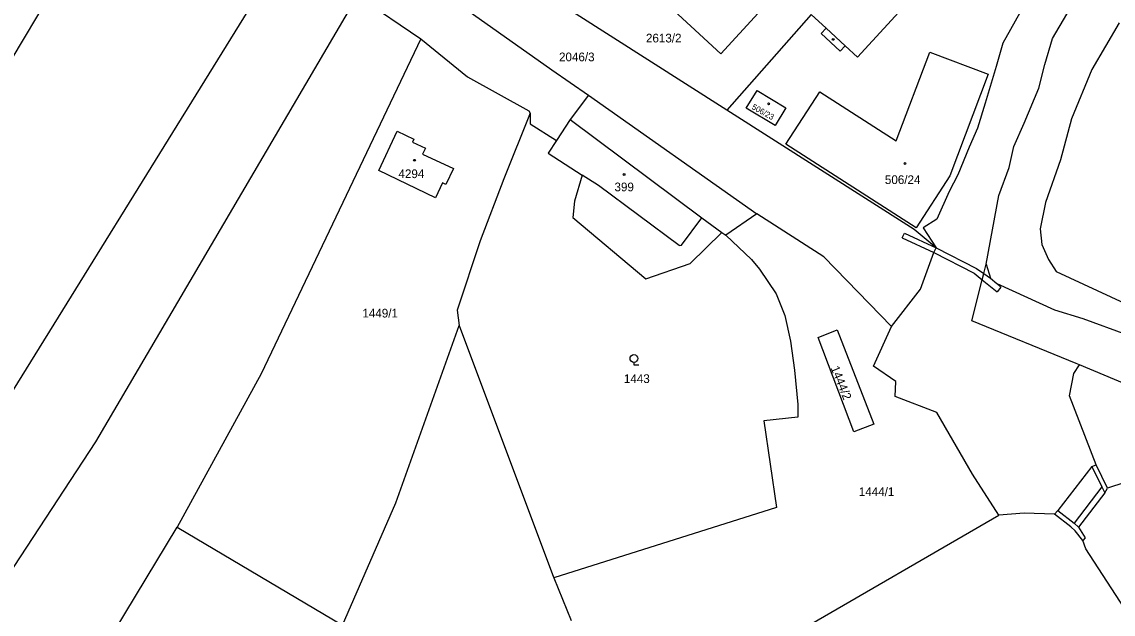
# Model space of a CAD drawing. Extents: x -679220 to -673243, y -1075091 to -1066557.
# Drawn here: x -677237.5 to -677024.2, y -1070909.6 to -1070793.9 of the extents above; entities that cross this region are included whole.
import ezdxf

# ---------------------------------------------------------------- set-up
doc = ezdxf.new("R2010")
doc.units = 0
for name, color, linetype in [('Hranice parcel', 7, 'Continuous'), ('Parcelní čísla', 7, 'Continuous'), ('Vnitřní kresba', 7, 'Continuous'), ('Značky budov', 7, 'Continuous'), ('Značky kultur', 7, 'Continuous')]:
    doc.layers.add(name, color=color, linetype=linetype)

msp = doc.modelspace()

# ---------------------------------------------------------------- linework, layer by layer
at = {"layer": 'Hranice parcel'}
for p, q in [((-677171.84, -1070788.87), (-677159.45, -1070797.23)), ((-677099.68, -1070811.19), (-677129.85, -1070791.98)), ((-677083.16, -1070792.51), (-677099.68, -1070811.19)), ((-677130.31, -1070813.04), (-677132.99, -1070817.11)), ((-677100.63, -1070835.07), (-677099.86, -1070835.63)), ((-677207.11, -1070892.64), (-677174.77, -1070911.8)), ((-677133.49, -1070902.55), (-677130.07, -1070910.86))]:
    msp.add_line(p, q, dxfattribs=at)
for points in [[(-677203.57, -1070759.78), (-677198.39, -1070762.15), (-677163.69, -1070784.55), (-677154.72, -1070788.54), (-677133.88, -1070803.28), (-677126.71, -1070808.28), (-677130.31, -1070813.04)], [(-677079.67, -1070777.1), (-677100.85, -1070800.17), (-677119.25, -1070783.14), (-677097.77, -1070760.15)], [(-677364.04, -1070987.23), (-677362.94, -1070980.54), (-677338.56, -1070950.82), (-677313.04, -1070919.03), (-677289.25, -1070883.76), (-677247.04, -1070813.86), (-677224.46, -1070776.16)], [(-677048.97, -1070841.27), (-677046.53, -1070827.88), (-677044.52, -1070822.41), (-677043.55, -1070818.31), (-677041.55, -1070813.73), (-677038.68, -1070806.91), (-677037.55, -1070802.28), (-677036.01, -1070797.18), (-677033.25, -1070792.43), (-677028.32, -1070784.52), (-677023.72, -1070776.62)], [(-677353.59, -1071009.21), (-677311.42, -1070962.52), (-677281.85, -1070927.39), (-677267.88, -1070909.25), (-677253.05, -1070888.24), (-677185.28, -1070778.87)], [(-677059.31, -1070777.52), (-677055.75, -1070780.81), (-677074.12, -1070800.85), (-677076.57, -1070798.6), (-677077.52, -1070799.64), (-677081.23, -1070796.22), (-677080.27, -1070795.18), (-677083.16, -1070792.51)], [(-677039.39, -1070786.77), (-677045.73, -1070798.1), (-677047.04, -1070802.64), (-677049.19, -1070809.83), (-677050.66, -1070814.68), (-677052.34, -1070818.42), (-677054.53, -1070823.8), (-677056.21, -1070827.09), (-677058.65, -1070832.51), (-677061.33, -1070834.18), (-677058.79, -1070838.11)], [(-677340.87, -1071024.47), (-677300.46, -1070979.79), (-677271.33, -1070945.13), (-677251.29, -1070919.02), (-677223.02, -1070875.98), (-677171.84, -1070788.87)], [(-677022.97, -1070794.1), (-677028.35, -1070803.23), (-677032.28, -1070812.9), (-677034.49, -1070820.9), (-677037.37, -1070829.22), (-677038.43, -1070834.4), (-677038.09, -1070837.4), (-677036.83, -1070840.36), (-677035.28, -1070842.73), (-677005.93, -1070856.29)], [(-677159.45, -1070797.23), (-677190.71, -1070862.68), (-677207.11, -1070892.64)], [(-677159.45, -1070797.23), (-677150.34, -1070804.67), (-677138.35, -1070811.34), (-677138.11, -1070811.79)], [(-677081.48, -1070807.61), (-677066.56, -1070817.17), (-677060.01, -1070799.83), (-677048.59, -1070804.17), (-677056.09, -1070823.99), (-677062.66, -1070834.18), (-677088.12, -1070817.82), (-677081.48, -1070807.61)], [(-677090.2, -1070814.2), (-677095.89, -1070810.83), (-677093.73, -1070807.34), (-677088.12, -1070810.73), (-677090.2, -1070814.2)], [(-677058.79, -1070838.11), (-677063.08, -1070834.48), (-677099.68, -1070811.19)], [(-677138.11, -1070811.79), (-677143.27, -1070824.61), (-677147.87, -1070836.71), (-677152.38, -1070850.24), (-677151.99, -1070853.28)], [(-677138.11, -1070811.79), (-677138.11, -1070813.87), (-677132.99, -1070817.11)], [(-677130.31, -1070813.04), (-677104.56, -1070832.23), (-677100.63, -1070835.07)], [(-677153.11, -1070822.6), (-677154.59, -1070825.7), (-677155.21, -1070825.41), (-677156.59, -1070828.29), (-677167.71, -1070822.98), (-677164.09, -1070815.28), (-677160.85, -1070816.84), (-677161.11, -1070817.41), (-677158.55, -1070818.62), (-677159.13, -1070819.8), (-677153.11, -1070822.6)], [(-677132.99, -1070817.11), (-677134.61, -1070819.57), (-677127.92, -1070823.86), (-677129.43, -1070828.99), (-677129.8, -1070832.15), (-677115.47, -1070844.14), (-677106.81, -1070841.14), (-677100.63, -1070835.07)], [(-677067.5, -1070853.44), (-677076.25, -1070844.46), (-677080.74, -1070839.83), (-677093.84, -1070831.44), (-677099.86, -1070835.63)], [(-677099.86, -1070835.63), (-677094.86, -1070840.34), (-677093.26, -1070842.27), (-677090.04, -1070847.06), (-677088.32, -1070851.27), (-677087.23, -1070856.33), (-677086.43, -1070862), (-677085.79, -1070868.68), (-677085.78, -1070871.18), (-677092.45, -1070871.86), (-677089.95, -1070888.83), (-677133.49, -1070902.55)], [(-677067.5, -1070853.44), (-677061.85, -1070846.17), (-677059.22, -1070839), (-677058.79, -1070838.11)], [(-677030.74, -1070860.94), (-677031.4, -1070860.66), (-677051.79, -1070852.33), (-677049.75, -1070844.31), (-677049.44, -1070843.12), (-677048.97, -1070841.27)], [(-677048.97, -1070841.27), (-677048.15, -1070843.99), (-677046.93, -1070845.02), (-677035.63, -1070850.17), (-677030.09, -1070851.88), (-677021.57, -1070855), (-677011.01, -1070859.1), (-677002.76, -1070862.36), (-676990.12, -1070867.28), (-676983.42, -1070869.86)], [(-677174.77, -1070911.8), (-677164.38, -1070887.87), (-677151.99, -1070853.28)], [(-677151.99, -1070853.28), (-677133.71, -1070901.92), (-677133.49, -1070902.55)], [(-677046.51, -1070890.3), (-677051.64, -1070882.27), (-677058.64, -1070870.25), (-677066.74, -1070867.15), (-677066.67, -1070864.21), (-677071.02, -1070861.17), (-677067.5, -1070853.44)], [(-677081.79, -1070855.6), (-677078.09, -1070854.08), (-677070.97, -1070872.55), (-677074.82, -1070874.01), (-677081.79, -1070855.6)], [(-676999.51, -1070876.63), (-677025.25, -1070885.02), (-677027.52, -1070880.46), (-677032.67, -1070866.98), (-677031.85, -1070862.65), (-677030.74, -1070860.94)], [(-676999.51, -1070876.63), (-677001.05, -1070873.4), (-677030.74, -1070860.94)], [(-677022.03, -1070908.42), (-677029.52, -1070896.85), (-677030.1, -1070895.25), (-677031.58, -1070893.38), (-677032.45, -1070892.61), (-677035.63, -1070890.11), (-677041.58, -1070889.89), (-677046.51, -1070890.3)], [(-677119.16, -1070937.01), (-677086.34, -1070913.35), (-677046.51, -1070890.3)], [(-677320.1, -1071047.08), (-677278.77, -1070997), (-677249.46, -1070958.04), (-677231.5, -1070933.09), (-677207.11, -1070892.64)]]:
    msp.add_lwpolyline(points, dxfattribs=at)
at = {"layer": 'Vnitřní kresba'}
for p, q in [((-677080.27, -1070795.18), (-677076.57, -1070798.6)), ((-677126.71, -1070808.28), (-677093.84, -1070831.44)), ((-677124.74, -1070825.9), (-677127.92, -1070823.86)), ((-677108.99, -1070837.61), (-677124.74, -1070825.9)), ((-677108.53, -1070837.54), (-677104.56, -1070832.23)), ((-677065.39, -1070836.14), (-677064.97, -1070835.23)), ((-677065.39, -1070836.14), (-677059.22, -1070839)), ((-677064.97, -1070835.23), (-677058.79, -1070838.11)), ((-677108.99, -1070837.61), (-677108.53, -1070837.54)), ((-677058.79, -1070838.11), (-677050.87, -1070842.15)), ((-677059.22, -1070839), (-677051.31, -1070843.04)), ((-677051.31, -1070843.04), (-677049.75, -1070844.31)), ((-677050.87, -1070842.15), (-677049.44, -1070843.12)), ((-677049.44, -1070843.12), (-677048.15, -1070843.99)), ((-677049.75, -1070844.31), (-677046.84, -1070846.67)), ((-677046.93, -1070845.02), (-677046.09, -1070845.79)), ((-677046.09, -1070845.79), (-677046.84, -1070846.67)), ((-677028.36, -1070880.78), (-677034.97, -1070889.36)), ((-677028.36, -1070880.78), (-677027.52, -1070880.46)), ((-677028.36, -1070880.78), (-677026.39, -1070884.74)), ((-677026.39, -1070884.74), (-677031.79, -1070891.86)), ((-677026.39, -1070884.74), (-677025.79, -1070885.94)), ((-677025.79, -1070885.94), (-677025.25, -1070885.02)), ((-677025.79, -1070885.94), (-677030.93, -1070892.63)), ((-677034.97, -1070889.36), (-677035.63, -1070890.11)), ((-677034.97, -1070889.36), (-677031.79, -1070891.86)), ((-677031.79, -1070891.86), (-677030.93, -1070892.63)), ((-677030.93, -1070892.63), (-677029.64, -1070894.72)), ((-677029.64, -1070894.72), (-677030.1, -1070895.25))]:
    msp.add_line(p, q, dxfattribs=at)
at = {"layer": 'Značky budov'}
for centre in [(-677078.89, -1070797.37), (-677091.5, -1070809.95), (-677160.72, -1070820.98), (-677064.85, -1070821.6), (-677119.75, -1070823.76)]:
    msp.add_circle(centre, 0.175, dxfattribs=at)
at = {"layer": 'Značky kultur'}
for p, q in [((-677117.84, -1070860.45), (-677117.84, -1070860.95)), ((-677117.84, -1070860.95), (-677116.84, -1070860.95))]:
    msp.add_line(p, q, dxfattribs=at)
msp.add_circle((-677117.84, -1070859.7), 0.75, dxfattribs=at)

# ---------------------------------------------------------------- texts
at = {"layer": 'Parcelní čísla'}
for s, p in [('2613/2', (-677115.48, -1070797.96)), ('2046/3', (-677132.47, -1070801.64)), ('4294', (-677163.85, -1070824.46)), ('506/24', (-677068.78, -1070825.62)), ('399', (-677121.63, -1070827.04)), ('1449/1', (-677170.9, -1070851.69)), ('1443', (-677119.79, -1070864.49)), ('1444/1', (-677073.88, -1070886.57))]:
    msp.add_text(s, height=1.7, dxfattribs=at).set_placement(p)
for s, height, rotation, p in [('506/23', 1.14, 331, (-677094.92, -1070810.9)), ('1444/2', 1.7, 292, (-677079.41, -1070861.54))]:
    msp.add_text(s, height=height, rotation=rotation, dxfattribs=at).set_placement(p)

doc.saveas('drawing.dxf')
